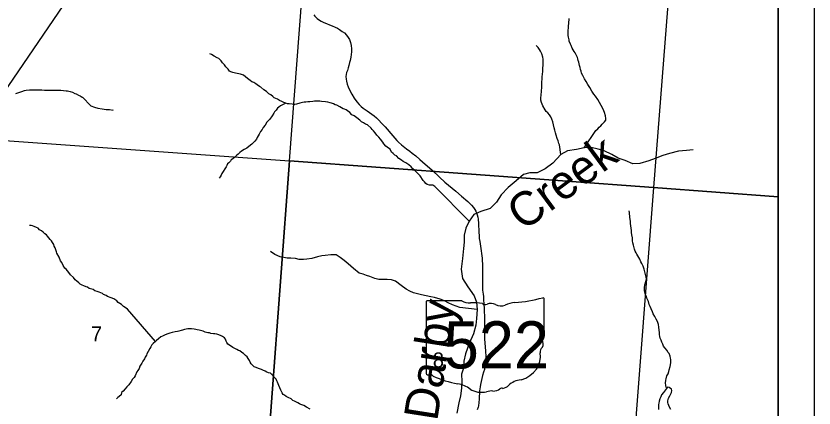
# Model space of a CAD drawing. Extents: x 0 to 34, y 0 to 22.
# Drawn here: x 6.769 to 9, y 18.72 to 19.816 of the extents above; entities that cross this region are included whole.
import ezdxf

# ---------------------------------------------------------------- set-up
doc = ezdxf.new("R2010")
doc.units = 0
for name, color, linetype in [('GM_X_Minor_River', 7, 'Continuous'), ('GM_X_Minor_River_Text', 7, 'Continuous'), ('GM_X_Section', 7, 'Continuous'), ('GM_X_Section_Text', 7, 'Continuous'), ('GM_X_State_Location', 7, 'Continuous'), ('GM_X_State_Route', 7, 'Continuous'), ('GM_X_State_Shield', 7, 'Continuous'), ('GM_X_Township_Road_Text', 7, 'Continuous'), ('GM_X_Unincorporated', 7, 'Continuous'), ('SH_Cut_Line', 7, 'Continuous'), ('SH_Data', 7, 'Continuous'), ('SH_Text', 7, 'Continuous')]:
    doc.layers.add(name, color=color, linetype=linetype)

msp = doc.modelspace()

# ---------------------------------------------------------------- linework, layer by layer
at = {"layer": 'GM_X_Minor_River'}
for points in [[(8.3579, 19.4469), (8.3905, 19.4956), (8.3959, 19.5005), (8.3994, 19.5046), (8.404, 19.5087), (8.4074, 19.5133), (8.4143, 19.5192), (8.4178, 19.5241), (8.4182, 19.5287), (8.4172, 19.5363), (8.4139, 19.5458), (8.4102, 19.5546), (8.4046, 19.5657), (8.4002, 19.5741), (8.3953, 19.5818), (8.389, 19.591), (8.3841, 19.5971), (8.3789, 19.6056), (8.373, 19.6159), (8.3674, 19.6243), (8.3633, 19.6324), (8.3588, 19.6396), (8.3555, 19.6454), (8.3536, 19.6492), (8.3503, 19.6557), (8.3488, 19.6614), (8.3474, 19.6656), (8.3463, 19.6717), (8.3448, 19.6774), (8.3437, 19.6813), (8.3427, 19.6862), (8.3412, 19.6908), (8.3401, 19.6954), (8.3386, 19.6996), (8.3368, 19.7034), (8.332, 19.7122), (8.3297, 19.716), (8.3271, 19.7206), (8.3242, 19.7256), (8.3216, 19.7328), (8.3197, 19.737), (8.3157, 19.7454), (8.3153, 19.7492), (8.3135, 19.7561), (8.3128, 19.7614), (8.3125, 19.7668), (8.3129, 19.7709), (8.313, 19.7759), (8.3134, 19.7819), (8.3139, 19.7876), (8.3143, 19.7941), (8.3147, 19.7983), (8.3156, 19.8047), (8.3158, 19.8082)], [(8.2922, 19.4286), (8.2888, 19.4551), (8.2869, 19.4589), (8.2847, 19.4662), (8.2822, 19.4734), (8.2796, 19.4822), (8.2774, 19.4891), (8.2756, 19.4959), (8.2738, 19.5032), (8.272, 19.5108), (8.2698, 19.5192), (8.2672, 19.5268), (8.2643, 19.5333), (8.2605, 19.539), (8.2561, 19.5448), (8.2515, 19.5487), (8.2489, 19.5536), (8.2422, 19.564), (8.24, 19.5693), (8.2378, 19.5739), (8.2367, 19.5804), (8.2364, 19.5857), (8.2369, 19.5948), (8.2378, 19.6043), (8.2391, 19.6176), (8.2392, 19.6286), (8.2397, 19.6415), (8.2405, 19.6453), (8.2414, 19.6529), (8.2418, 19.6605), (8.2423, 19.67), (8.2432, 19.6776), (8.2433, 19.6897), (8.243, 19.6947), (8.2419, 19.7), (8.2394, 19.7099), (8.2353, 19.7176), (8.2323, 19.7222), (8.2293, 19.7272), (8.2235, 19.7331)], [(7.462, 19.6095), (7.4541, 19.6161), (7.4503, 19.6184), (7.4435, 19.6234), (7.4394, 19.6254), (7.4338, 19.63), (7.4288, 19.6316), (7.4236, 19.6355), (7.4161, 19.6409), (7.4108, 19.6455), (7.4052, 19.6498), (7.3972, 19.6529), (7.3927, 19.6537), (7.3878, 19.6549), (7.3832, 19.6557), (7.3791, 19.6569), (7.3753, 19.6574), (7.37, 19.659), (7.3658, 19.6613), (7.3621, 19.6667), (7.3557, 19.6736), (7.352, 19.6793), (7.3467, 19.6843), (7.343, 19.6901), (7.3366, 19.6962), (7.3317, 19.6986), (7.3231, 19.7036), (7.3159, 19.7083), (7.3117, 19.7093)], [(6.7691, 19.5989), (6.7744, 19.6007), (6.7801, 19.6029), (6.7859, 19.6044), (6.7935, 19.6069), (6.798, 19.608), (6.8068, 19.6094), (6.8231, 19.6092), (6.8288, 19.6088), (6.8333, 19.6087), (6.8375, 19.6087), (6.8421, 19.609), (6.8489, 19.6085), (6.8735, 19.6082), (6.8804, 19.6085)], [(6.8804, 19.6085), (6.8948, 19.6083), (6.902, 19.6075), (6.9099, 19.6066), (6.9137, 19.6062), (6.9213, 19.6042), (6.9277, 19.6026), (6.9337, 19.5987), (6.9375, 19.5979), (6.9439, 19.594), (6.9492, 19.5921), (6.9545, 19.5886), (6.9553, 19.5882)], [(8.0357, 19.242), (7.9403, 19.339), (7.9346, 19.3422), (7.9305, 19.343), (7.9248, 19.343), (7.9187, 19.3443), (7.9146, 19.3473), (7.9112, 19.3516), (7.9071, 19.3558), (7.8989, 19.3684), (7.8955, 19.3723), (7.8907, 19.3769), (7.8835, 19.3842), (7.879, 19.3881), (7.8738, 19.3935), (7.8674, 19.3996), (7.8595, 19.4047), (7.852, 19.4089), (7.8471, 19.4124), (7.8395, 19.4174), (7.8328, 19.4248), (7.8283, 19.4267), (7.8234, 19.4313), (7.8189, 19.4348), (7.8155, 19.4428), (7.8106, 19.4459), (7.8031, 19.4513), (7.7979, 19.4582), (7.7949, 19.4632), (7.7882, 19.4713), (7.7837, 19.4763), (7.7784, 19.4828), (7.7736, 19.4893), (7.7687, 19.494), (7.7653, 19.4978), (7.762, 19.502), (7.7515, 19.5113), (7.7465, 19.5132), (7.7405, 19.5167), (7.7352, 19.5195), (7.7307, 19.5245), (7.7217, 19.5306), (7.7146, 19.5361), (7.7085, 19.5396), (7.7025, 19.5457), (7.6958, 19.5504), (7.692, 19.5531), (7.6878, 19.5546), (7.6837, 19.5558), (7.6788, 19.5585), (7.675, 19.562), (7.6664, 19.5663), (7.6618, 19.5675), (7.6565, 19.5702), (7.6516, 19.5714), (7.6478, 19.573), (7.6414, 19.5746), (7.6346, 19.5754), (7.6236, 19.5767), (7.6191, 19.5775), (7.6137, 19.5772), (7.6099, 19.5773), (7.6039, 19.577), (7.5993, 19.5766), (7.591, 19.5756), (7.5856, 19.5757), (7.5792, 19.575), (7.575, 19.5747), (7.5701, 19.5736), (7.5628, 19.5714), (7.5533, 19.5689), (7.5488, 19.5682), (7.545, 19.5682), (7.5412, 19.5686), (7.5328, 19.5699), (7.5283, 19.5703), (7.5241, 19.5719), (7.5177, 19.5735), (7.5121, 19.5762), (7.5064, 19.5793), (7.5004, 19.5828), (7.4909, 19.5871), (7.4872, 19.5902), (7.4819, 19.5952), (7.4766, 19.5979), (7.4699, 19.6041), (7.462, 19.6095)], [(6.9553, 19.5882), (6.9782, 19.5643), (6.9887, 19.5605), (6.9986, 19.5581), (7.0099, 19.5558), (7.0213, 19.5542), (7.0311, 19.5537), (7.041, 19.5525), (7.0406, 19.5525)], [(7.5241, 19.5719), (7.5089, 19.5645), (7.5043, 19.5604), (7.5005, 19.5574), (7.4962, 19.5521), (7.4916, 19.548), (7.4901, 19.5442), (7.4854, 19.5363), (7.4785, 19.5269), (7.4704, 19.5186), (7.4661, 19.5107), (7.4604, 19.5035), (7.4573, 19.4986), (7.4527, 19.493), (7.4495, 19.4851), (7.4461, 19.4809), (7.4437, 19.4756), (7.4414, 19.4711), (7.4368, 19.4655), (7.4291, 19.4576), (7.4249, 19.4546), (7.4146, 19.4456), (7.4069, 19.4423), (7.3993, 19.4374), (7.3955, 19.4341), (7.3909, 19.4296), (7.387, 19.4262), (7.3813, 19.4213), (7.3751, 19.4165), (7.3709, 19.4131), (7.3694, 19.4093), (7.3648, 19.4052), (7.3609, 19.4018), (7.3586, 19.398), (7.3567, 19.3935), (7.3532, 19.3878), (7.3489, 19.3811), (7.3451, 19.375), (7.3431, 19.3701), (7.3397, 19.3656), (7.3373, 19.3618)], [(8.662, 19.4416), (8.6434, 19.4397), (8.6214, 19.4372), (8.5963, 19.4312), (8.577, 19.4252), (8.5561, 19.4174), (8.5382, 19.411), (8.5127, 19.4035), (8.4934, 19.4021), (8.4722, 19.4117), (8.4529, 19.4183), (8.4348, 19.4283), (8.4136, 19.4382), (8.3962, 19.4429), (8.3773, 19.4483), (8.3579, 19.4469), (8.3359, 19.4421), (8.3112, 19.4384), (8.2922, 19.4286), (8.27, 19.4037), (8.2483, 19.3882), (8.2259, 19.3773), (8.2054, 19.377), (8.1883, 19.3722), (8.1673, 19.3545), (8.1452, 19.3356), (8.1257, 19.3156), (8.1127, 19.2951), (8.0951, 19.277), (8.0685, 19.2688), (8.0491, 19.2605), (8.0357, 19.242), (8.0265, 19.2227), (8.0222, 19.2025), (8.0217, 19.1836), (8.0204, 19.1657), (8.0172, 19.138), (8.0136, 19.1077), (8.0172, 19.0814), (8.0326, 19.0586), (8.0499, 19.0334), (8.0566, 19.0152), (8.0583, 18.9947), (8.0563, 18.97), (8.0546, 18.951), (8.048, 18.9271), (8.0357, 18.8998), (8.0257, 18.8714), (8.021, 18.8509), (8.0205, 18.8312), (8.015, 18.8138), (8.0153, 18.7936), (8.0148, 18.7754), (8.0116, 18.7534), (8.0073, 18.7344), (8.0014, 18.7052)], [(8.5871, 18.7765), (8.5857, 18.7838), (8.585, 18.7887), (8.5855, 18.7974), (8.587, 18.8012), (8.589, 18.8095), (8.5921, 18.8156), (8.5941, 18.8216), (8.5949, 18.8266), (8.5977, 18.8357), (8.5993, 18.8455), (8.5997, 18.8501), (8.5998, 18.855), (8.5991, 18.8588), (8.598, 18.8649), (8.5947, 18.8722), (8.5917, 18.876), (8.5891, 18.8806), (8.5827, 18.8883), (8.579, 18.8925), (8.5771, 18.8982), (8.5746, 18.9036), (8.5727, 18.9093), (8.5701, 18.915), (8.5694, 18.9196), (8.568, 18.9253), (8.5677, 18.9306), (8.567, 18.9371), (8.5663, 18.9455), (8.5653, 18.9535), (8.5623, 18.9611), (8.559, 18.968), (8.5549, 18.9753), (8.5501, 18.9833), (8.5486, 18.9886), (8.5449, 18.997), (8.5416, 19.0035), (8.5393, 19.0089), (8.5372, 19.0169), (8.5331, 19.0268), (8.5309, 19.0329), (8.5287, 19.0368), (8.5268, 19.0436), (8.5261, 19.0474), (8.5262, 19.0566), (8.5275, 19.0638), (8.5302, 19.0736), (8.5314, 19.08), (8.5311, 19.0857), (8.5293, 19.093), (8.5275, 19.0999), (8.5249, 19.1082), (8.522, 19.1163), (8.5187, 19.1235), (8.5161, 19.1285), (8.5127, 19.1354), (8.5105, 19.1403), (8.5075, 19.1449), (8.5046, 19.1499), (8.5027, 19.1537), (8.5005, 19.1583), (8.4986, 19.1633), (8.495, 19.1747), (8.4935, 19.1812), (8.4928, 19.1873), (8.4922, 19.1953), (8.4911, 19.2033), (8.4901, 19.2098), (8.4894, 19.2155), (8.4887, 19.2219), (8.4876, 19.2288), (8.487, 19.2356), (8.4866, 19.2421), (8.4859, 19.247), (8.4856, 19.2527), (8.4849, 19.2569), (8.4846, 19.2611), (8.4839, 19.2657), (8.4836, 19.2706)], [(7.1594, 18.9051), (7.0808, 18.9957), (7.0771, 18.9984), (7.0695, 19.0031), (7.0643, 19.0092), (7.0552, 19.0147), (7.0515, 19.0189), (7.0425, 19.0247), (7.0357, 19.0275), (7.0255, 19.0314), (7.0217, 19.0337), (7.0145, 19.0368), (7.0108, 19.0395), (7.0021, 19.0435), (6.9964, 19.045), (6.99, 19.0474), (6.9855, 19.0505), (6.9779, 19.0525), (6.9741, 19.0541), (6.9696, 19.0575), (6.9658, 19.0587), (6.959, 19.0611), (6.9545, 19.0634), (6.9492, 19.0658), (6.9447, 19.07), (6.9398, 19.0739), (6.9353, 19.0777), (6.9305, 19.0843), (6.9218, 19.0916), (6.9173, 19.0985), (6.9099, 19.1073), (6.9061, 19.1108), (6.9013, 19.1184), (6.8976, 19.1265), (6.8942, 19.1311), (6.8901, 19.141), (6.8838, 19.1525), (6.8824, 19.1563), (6.8805, 19.162), (6.8787, 19.1674), (6.8765, 19.1723), (6.875, 19.1769), (6.8716, 19.1819), (6.869, 19.1869), (6.8649, 19.1911), (6.8574, 19.2003), (6.8544, 19.2041), (6.8503, 19.2069), (6.8458, 19.2111), (6.8409, 19.215), (6.8356, 19.2181), (6.8311, 19.2219), (6.8266, 19.2239), (6.8206, 19.2266), (6.8157, 19.2286), (6.8115, 19.2294), (6.8069, 19.2298)], [(8.0583, 18.9947), (8.0101, 19.0004), (8.0002, 19.0039), (7.9896, 19.0081), (7.9774, 19.0134), (7.9668, 19.0191), (7.955, 19.0237), (7.939, 19.0286), (7.9288, 19.0305), (7.9162, 19.0332), (7.9025, 19.0359), (7.8919, 19.0389), (7.8801, 19.042), (7.8702, 19.0458), (7.86, 19.0522), (7.8463, 19.0621), (7.83, 19.0743), (7.8193, 19.0777), (7.8068, 19.0789), (7.784, 19.0789), (7.7722, 19.082), (7.7589, 19.0869), (7.7494, 19.0903), (7.7395, 19.0934), (7.7285, 19.0968), (7.7126, 19.1097), (7.6977, 19.1223), (7.6863, 19.1322), (7.6757, 19.1402), (7.6647, 19.1478), (7.6491, 19.1482), (7.6339, 19.1463), (7.624, 19.1452), (7.6119, 19.1425), (7.5966, 19.138), (7.5826, 19.1357), (7.5727, 19.1345), (7.5613, 19.1349), (7.5503, 19.1376), (7.5377, 19.1384), (7.5275, 19.1388), (7.5077, 19.1418), (7.4933, 19.1487), (7.4811, 19.1574)], [(7.5917, 18.7161), (7.5815, 18.7223), (7.574, 18.7266), (7.566, 18.7293), (7.5619, 18.7317), (7.557, 18.734), (7.5483, 18.7383), (7.5434, 18.7403), (7.5389, 18.7449), (7.5298, 18.7492), (7.5245, 18.7515), (7.52, 18.7558), (7.5159, 18.7577), (7.5133, 18.7619), (7.5096, 18.7696), (7.5066, 18.7761), (7.504, 18.7822), (7.5022, 18.7868), (7.5, 18.7921), (7.4981, 18.7959), (7.4963, 18.8001), (7.4929, 18.8044), (7.4884, 18.8097), (7.4847, 18.8136), (7.4805, 18.8167), (7.4752, 18.8183), (7.4703, 18.8202), (7.4658, 18.8226), (7.4594, 18.8253), (7.4556, 18.8276), (7.4477, 18.83), (7.4405, 18.8331), (7.4356, 18.8351), (7.4311, 18.8389), (7.427, 18.8432), (7.4243, 18.8474), (7.4221, 18.8527), (7.4188, 18.8581), (7.4154, 18.8623), (7.4109, 18.8666), (7.4049, 18.8716), (7.4011, 18.8747), (7.3947, 18.8793), (7.391, 18.8805), (7.3864, 18.8836), (7.3812, 18.8863), (7.3755, 18.889), (7.3714, 18.8914), (7.3616, 18.8983), (7.359, 18.9025), (7.3571, 18.9068), (7.3553, 18.9117), (7.3523, 18.9155), (7.347, 18.9194), (7.3433, 18.9217), (7.3365, 18.9245), (7.3308, 18.9257), (7.3255, 18.9269), (7.3213, 18.9273), (7.3141, 18.9278), (7.31, 18.9294), (7.3054, 18.9298), (7.2978, 18.9314), (7.2926, 18.9342), (7.2812, 18.937), (7.2763, 18.9382), (7.2718, 18.939), (7.2676, 18.9398), (7.2596, 18.9407), (7.2551, 18.9407), (7.2501, 18.9408), (7.2406, 18.939), (7.2353, 18.9372), (7.2315, 18.9364), (7.225, 18.9346), (7.2212, 18.9339), (7.2148, 18.9329), (7.2064, 18.9307), (7.1992, 18.9289), (7.1938, 18.9274), (7.1866, 18.9241), (7.1793, 18.9204), (7.1744, 18.9182), (7.1675, 18.9133), (7.1621, 18.9088), (7.1594, 18.9051), (7.1533, 18.8998), (7.1487, 18.8961), (7.146, 18.8908), (7.144, 18.8863), (7.1386, 18.878), (7.1355, 18.8712), (7.1343, 18.867), (7.1301, 18.8617), (7.1282, 18.8568), (7.1239, 18.8508), (7.1216, 18.8447), (7.1158, 18.8368)], [(7.1158, 18.8368), (7.1134, 18.8304), (7.1096, 18.8244), (7.1076, 18.8206), (7.1029, 18.8096), (7.0995, 18.8051), (7.0952, 18.8002), (7.0918, 18.7938), (7.0848, 18.784), (7.0795, 18.7792), (7.0748, 18.7735), (7.0687, 18.7671), (7.0645, 18.7626), (7.0633, 18.7566), (7.0579, 18.7521), (7.0541, 18.7487), (7.0502, 18.7457)], [(8.5825, 18.7667), (8.579, 18.7629), (8.574, 18.7562), (8.572, 18.7509), (8.5689, 18.7452), (8.567, 18.7384), (8.5661, 18.7331), (8.5657, 18.7293), (8.5653, 18.724), (8.5652, 18.7198), (8.5656, 18.7156)], [(8.5993, 18.7156), (8.5956, 18.7221), (8.5945, 18.7266), (8.5923, 18.7312), (8.5916, 18.735), (8.5913, 18.74), (8.5929, 18.7468), (8.5967, 18.7532), (8.599, 18.7577), (8.6018, 18.7634), (8.6026, 18.7683), (8.6015, 18.7722), (8.5955, 18.7768), (8.5905, 18.7776), (8.5852, 18.7705), (8.5825, 18.7667)]]:
    msp.add_lwpolyline(points, dxfattribs=at)
at = {"layer": 'GM_X_Section'}
for points in [[(7.6117, 20.4271), (8.6303, 20.3481), (8.5509, 19.3356), (7.5335, 19.4104)], [(6.5282, 19.4822), (7.5335, 19.4104), (7.4583, 18.399), (6.4594, 18.4632)], [(7.5335, 19.4104), (8.5509, 19.3356), (8.4739, 18.3269), (7.4583, 18.399)]]:
    msp.add_lwpolyline(points, close=True, dxfattribs=at)
at = {"layer": 'GM_X_State_Route'}
msp.add_lwpolyline([(7.6018, 19.8191), (7.6049, 19.8146), (7.608, 19.8113), (7.6109, 19.8087), (7.6153, 19.8055), (7.6223, 19.8014), (7.6302, 19.7976), (7.6374, 19.7945), (7.6456, 19.7912), (7.6532, 19.788), (7.6617, 19.7842), (7.6681, 19.781), (7.6739, 19.7776), (7.6813, 19.7725), (7.6873, 19.768), (7.6931, 19.7622), (7.6979, 19.7558), (7.7015, 19.7495), (7.7045, 19.7411), (7.7063, 19.7326), (7.7071, 19.724), (7.707, 19.7154), (7.7063, 19.7078), (7.7049, 19.7), (7.7033, 19.6911), (7.702, 19.6851), (7.6999, 19.677), (7.6981, 19.6701), (7.6956, 19.6631), (7.6936, 19.6577), (7.6926, 19.652), (7.6915, 19.646), (7.6919, 19.6391), (7.6929, 19.6331), (7.6952, 19.6249), (7.6981, 19.6171), (7.7022, 19.6074), (7.7077, 19.5966), (7.7145, 19.5858), (7.722, 19.5756), (7.7287, 19.5682), (7.7344, 19.5625), (7.7397, 19.5581), (7.7456, 19.5537), (7.751, 19.55), (7.7574, 19.5456), (7.7644, 19.5408), (7.7705, 19.5365), (7.777, 19.5308), (7.7831, 19.5251), (7.7921, 19.5154), (7.8015, 19.5054), (7.8231, 19.4809), (7.8339, 19.4676), (7.8389, 19.4625), (7.8467, 19.4552), (7.8609, 19.4438), (7.8698, 19.4375), (7.8769, 19.4321), (7.8866, 19.4243), (7.8985, 19.4146), (7.9061, 19.4079), (7.9324, 19.3846), (7.9529, 19.3649), (7.968, 19.351), (7.9987, 19.3255), (8.0146, 19.3119), (8.0319, 19.2967), (8.0422, 19.2864), (8.0479, 19.2804), (8.0518, 19.2749), (8.0548, 19.2697), (8.0567, 19.2656), (8.0587, 19.2592), (8.0605, 19.2533), (8.0615, 19.2473), (8.0623, 19.2355), (8.0631, 19.211), (8.0636, 19.2007), (8.0644, 19.1939), (8.0657, 19.1848), (8.0675, 19.1722), (8.072, 19.1387), (8.0728, 19.1319), (8.0732, 19.1215), (8.0733, 19.1072), (8.0731, 19.0827), (8.073, 19.0724), (8.073, 19.066), (8.073, 19.0601), (8.0731, 19.0554), (8.0738, 19.049), (8.0751, 19.0383), (8.0757, 19.0317), (8.0765, 19.0213), (8.0768, 19.0116), (8.0776, 18.9959), (8.0787, 18.9694), (8.0791, 18.9551), (8.0793, 18.9132), (8.0819, 18.8786), (8.0828, 18.8634), (8.0823, 18.8537), (8.0809, 18.8394), (8.0785, 18.8271), (8.0763, 18.8194), (8.0736, 18.8101), (8.0694, 18.7934), (8.0676, 18.7856), (8.0666, 18.7787), (8.0653, 18.7676), (8.0642, 18.744), (8.0622, 18.7261), (8.0613, 18.7219), (8.0589, 18.7145)], dxfattribs=at)
at = {"layer": 'GM_X_State_Shield'}
for p, q in [((7.9161, 19.0161), (7.9161, 18.816)), ((8.0159, 19.0196), (7.9194, 19.0196)), ((8.2457, 18.9199), (8.2457, 19.0246)), ((8.2457, 18.9199), (8.2457, 18.9199))]:
    msp.add_line(p, q, dxfattribs=at)
for centre, major_axis, start_param, end_param in [((8.1283, 19.2924), (0.3495, 0), 4.814394, 5.042369), ((8.2421, 19.025), (0.00367, 0), 6.141152, 7.989035), ((7.9199, 19.0166), (0.00382, 0), 1.712693, 3.28349), ((8.0389, 19.0428), (0.037, 0), 4.042523, 4.731795), ((8.0512, 18.9072), (0.133, 0), 1.404758, 1.657858), ((8.0814, 19.0176), (0.0107, 0), 3.836095, 5.185415), ((8.097, 18.9945), (0.0222, 0), 0.950623, 2.079405), ((8.1257, 19.0262), (0.0267, 0), 4.081561, 5.145723), ((8.1729, 18.9585), (0.0703, 0), 1.699011, 2.107814), ((8.2449, 18.9122), (0.00568, 0), 1.883978, 3.671073), ((8.2418, 18.9195), (0.00393, 0), 5.05454, 6.418171), ((8.2088, 18.8989), (0.0341, 0), 5.934695, 6.695948), ((8.1479, 18.8627), (0.0874, 0), 5.101752, 6.440018), ((8.2589, 18.8761), (0.0248, 0), 2.387724, 3.262537), ((7.92, 18.8156), (0.00385, 0), 3.00124, 4.508301), ((7.9205, 18.8361), (0.0294, 0), 4.665946, 4.897461), ((7.9266, 18.8045), (0.0106, 0), 0.519207, 1.627899), ((8.0604, 18.9843), (0.2524, 0), 4.195997, 4.488961), ((7.9851, 18.7261), (0.079, 0), 0.823519, 1.323587), ((8.1241, 18.7966), (0.0282, 0), 4.937069, 5.64225), ((8.1848, 18.7598), (0.0479, 0), 1.647645, 2.488434), ((8.0705, 18.8035), (0.0501, 0), 4.026481, 4.996735), ((8.0995, 18.7343), (0.0412, 0), 1.495662, 1.94098), ((8.1032, 18.7885), (0.0267, 0), 4.691044, 5.507374), ((8.1273, 18.7691), (0.00752, 0), 1.147584, 2.315152)]:
    msp.add_ellipse(centre, major_axis=major_axis, ratio=0.8, start_param=start_param, end_param=end_param, dxfattribs=at)
at = {"layer": 'GM_X_Township_Road_Text'}
for points in [[(8.9, 19.3099), (8.9, 20.328), (8.6303, 20.3481), (8.5509, 19.3356)], [(8.9, 18.2954), (8.9, 19.3099), (8.5509, 19.3356), (8.4739, 18.3269)]]:
    msp.add_lwpolyline(points, close=True, dxfattribs=at)
at = {"layer": 'GM_X_Unincorporated'}
msp.add_lwpolyline([(8.9, 14.2264), (8.9, 20.3234), (8.6245, 20.3436), (7.6038, 20.4229), (7.3955, 20.4364), (6.962, 20.4644), (6.8381, 20.4724), (6.7584, 20.4776), (6.6718, 20.4832), (6.6484, 20.4847), (4.3099, 20.6409), (3.8602, 20.6728), (3.5651, 20.6937), (3.5462, 20.4144), (3.5457, 20.4056), (3.5456, 20.4047), (3.5099, 19.8769)], dxfattribs=at)
at = {"layer": 'SH_Cut_Line'}
msp.add_lwpolyline([(8.9, 14.1), (8.9, 20.9), (6.769, 20.9), (6.6568, 20.5136), (6.6484, 20.4847), (4.3099, 20.6409), (3.8602, 20.6728), (3.5651, 20.6937), (3.5462, 20.4144), (3.5457, 20.4056), (3.5456, 20.4047), (3.5099, 19.8769), (3.4599, 19.1361), (3.4595, 19.1305), (3.4011, 18.2653), (3.709, 17.484), (3.7367, 17.4136), (3.972, 16.8916), (4.0882, 16.6114), (4.2937, 16.1161)], dxfattribs=at)
at = {"layer": 'SH_Data'}
for p, q in [((9, 21), (9, 14)), ((8.9, 20.9), (8.9, 14.1))]:
    msp.add_line(p, q, dxfattribs=at)
at = {"layer": 'SH_Text'}
msp.add_lwpolyline([(7.0694, 20.091), (7.0694, 20.9), (5.2191, 17.3772)], close=True, dxfattribs=at)

# ---------------------------------------------------------------- texts
at = {"layer": 'GM_X_Minor_River_Text'}
for s, height, rotation, p in [('Creek', 0.0947, 36.4689, (8.1873, 19.212)), ('Darby', 0.09469, 81.1077, (7.9466, 18.6809))]:
    msp.add_text(s, height=height, rotation=rotation, dxfattribs=at).set_placement(p)
at = {"layer": 'GM_X_Section_Text'}
for s, p in [('7', (6.9791, 18.906)), ('8', (7.9345, 18.8329))]:
    msp.add_text(s, height=0.0419, rotation=0, dxfattribs=at).set_placement(p)
at = {"layer": 'GM_X_State_Location'}
for s in ['s', 'r']:
    msp.add_text(s, height=0.000189, dxfattribs=at).set_placement((8.0772, 18.9028))
msp.add_text('522', height=0.000189, rotation=0, dxfattribs=at).set_placement((8.0104, 18.889))
at = {"layer": 'GM_X_State_Shield'}
msp.add_text('522', height=0.13184, dxfattribs=at).set_placement((7.9651, 18.8301))

doc.saveas('drawing.dxf')
